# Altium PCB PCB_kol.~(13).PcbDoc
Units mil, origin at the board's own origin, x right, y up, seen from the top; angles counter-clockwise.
Board outline 2952.76 x 2952.76 mil, 4 copper layers (Top Layer, Mid 1 - POWER, Mid 2 - GND, Bottom Layer), stack 38.362 mil thick; 6 components, 21 nets, 136 pads, 182 vias.
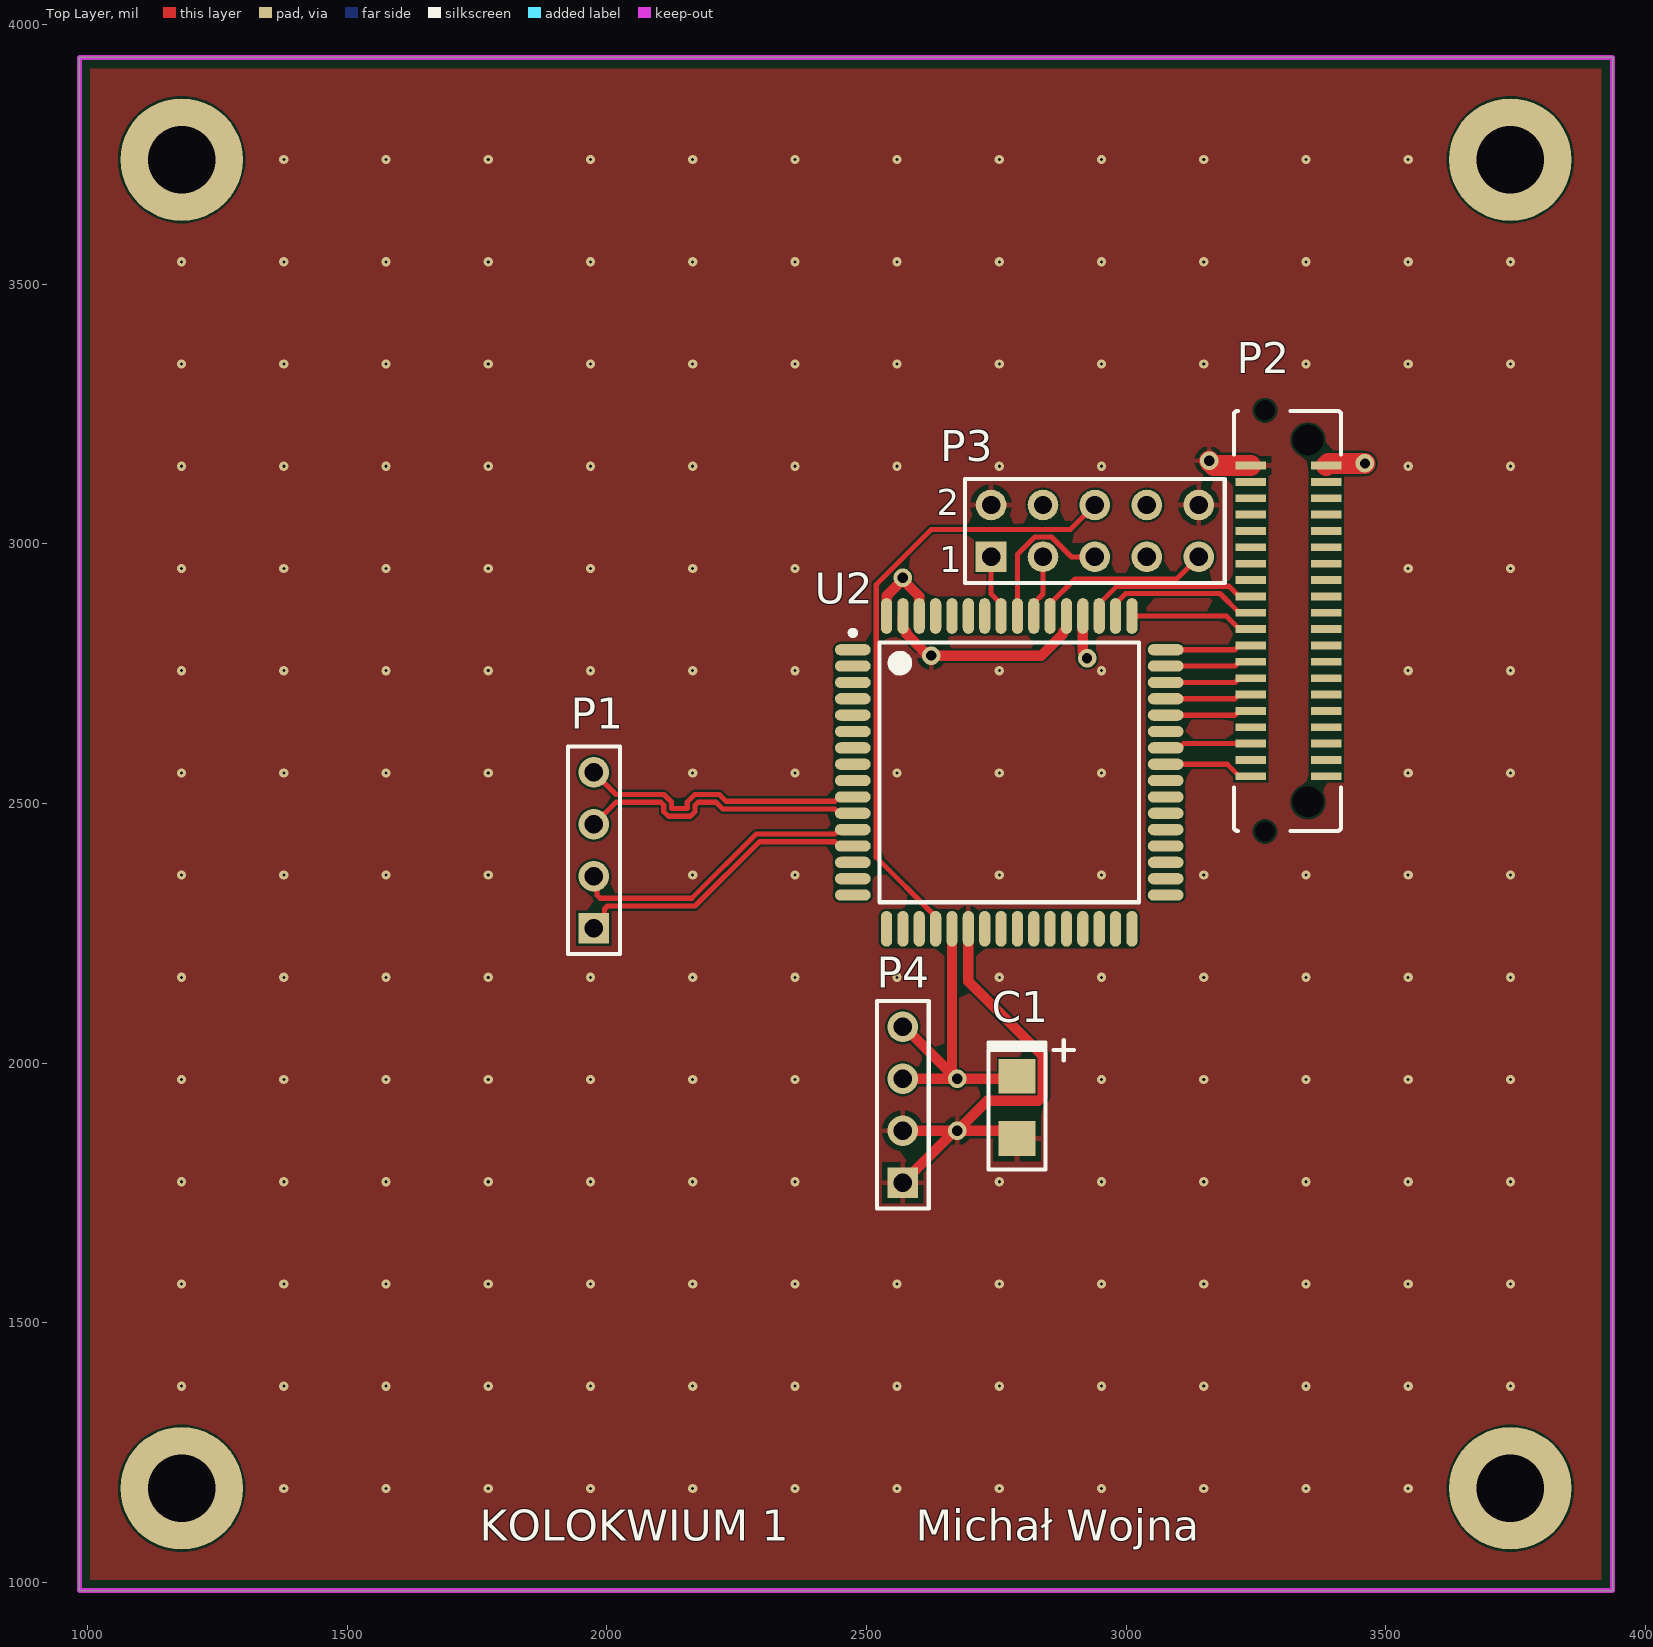
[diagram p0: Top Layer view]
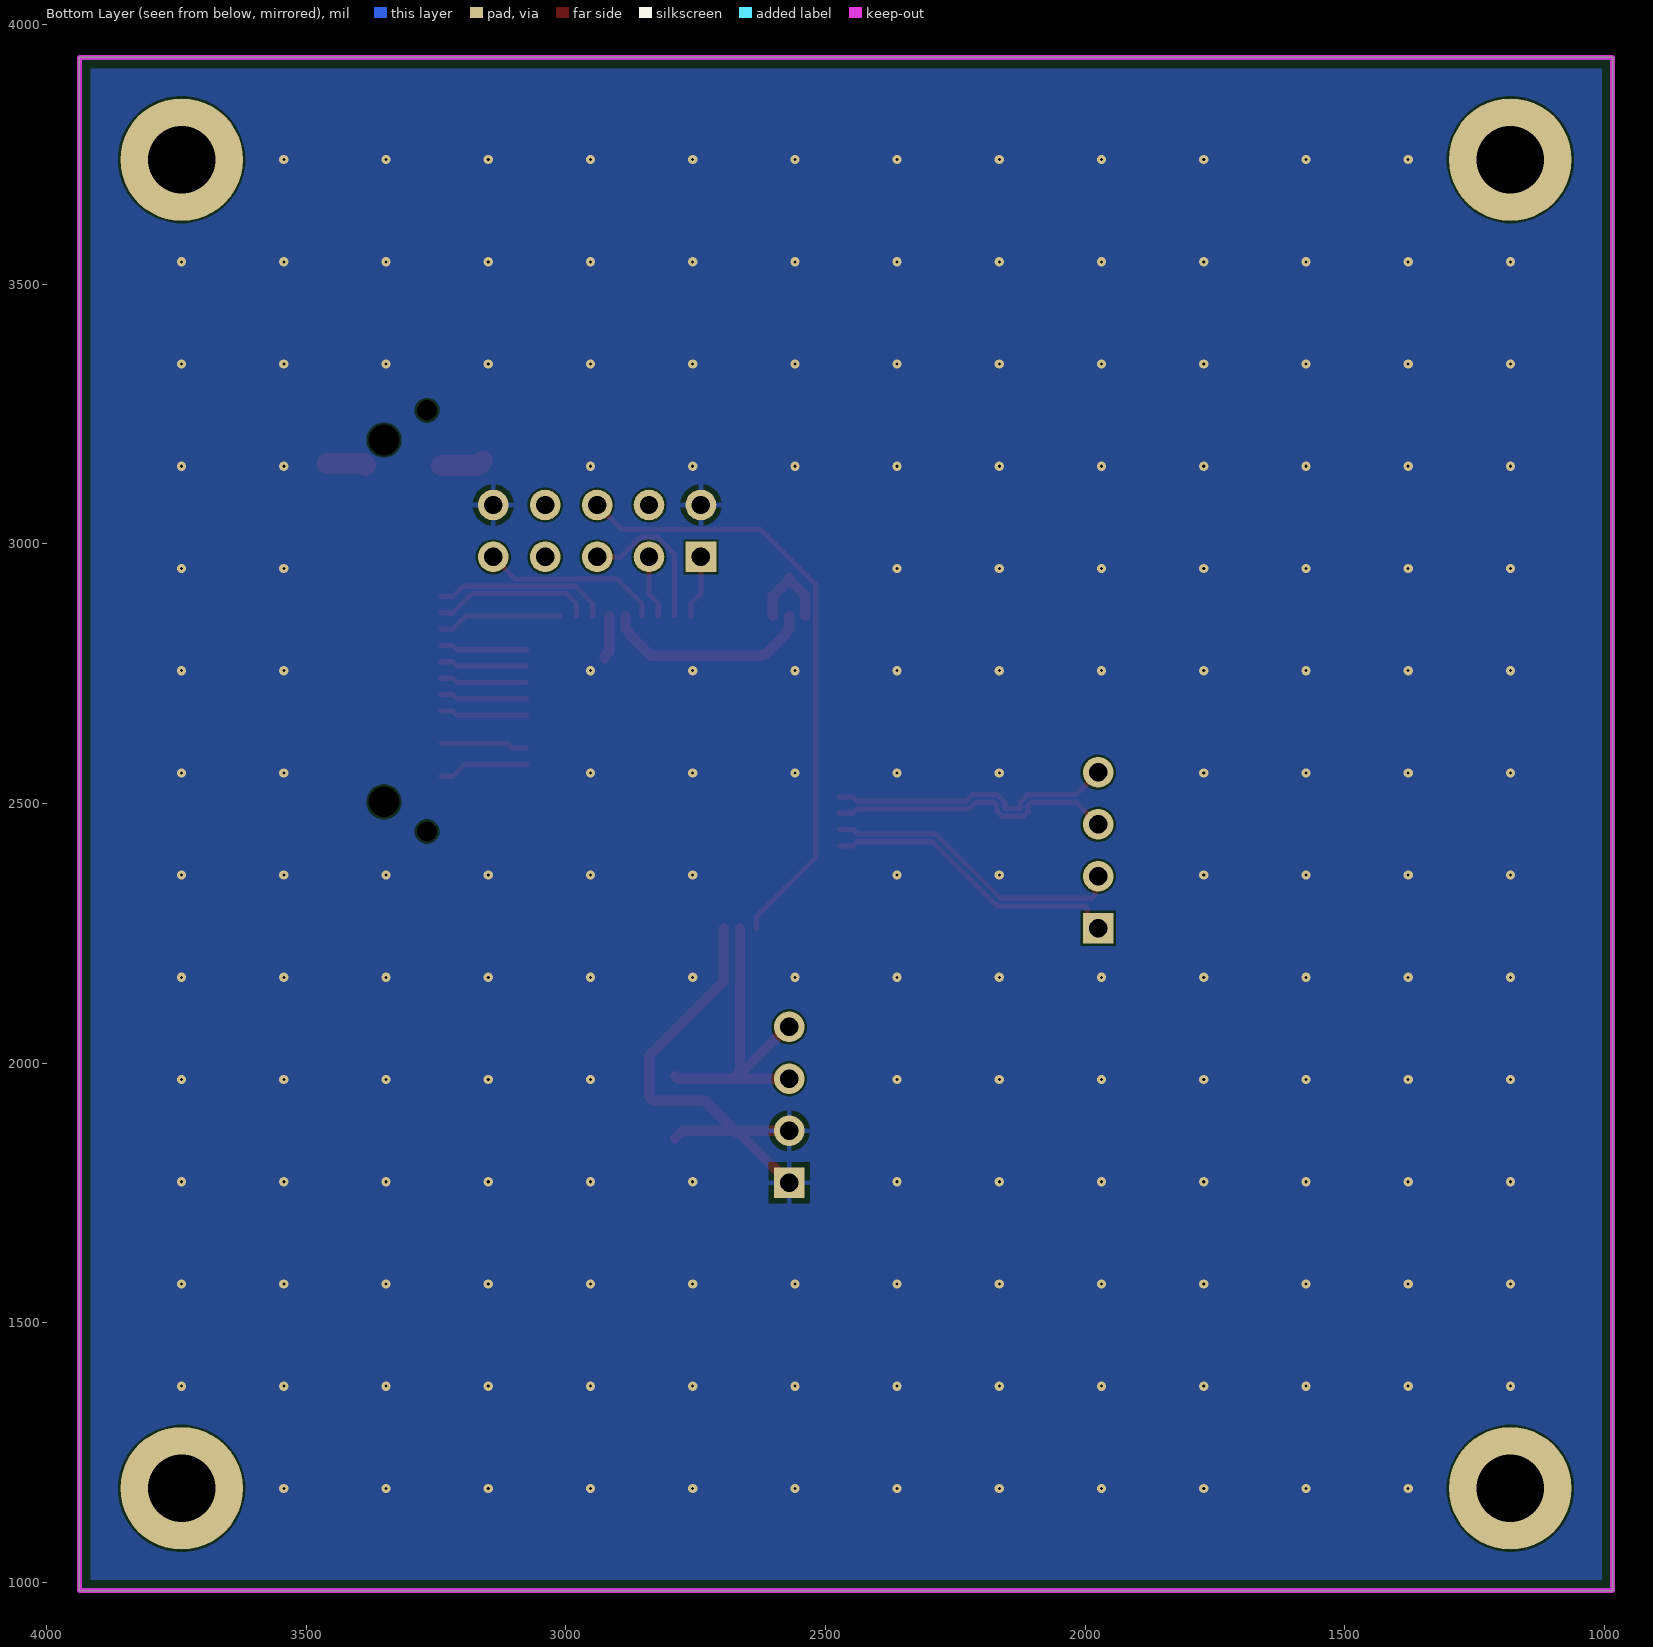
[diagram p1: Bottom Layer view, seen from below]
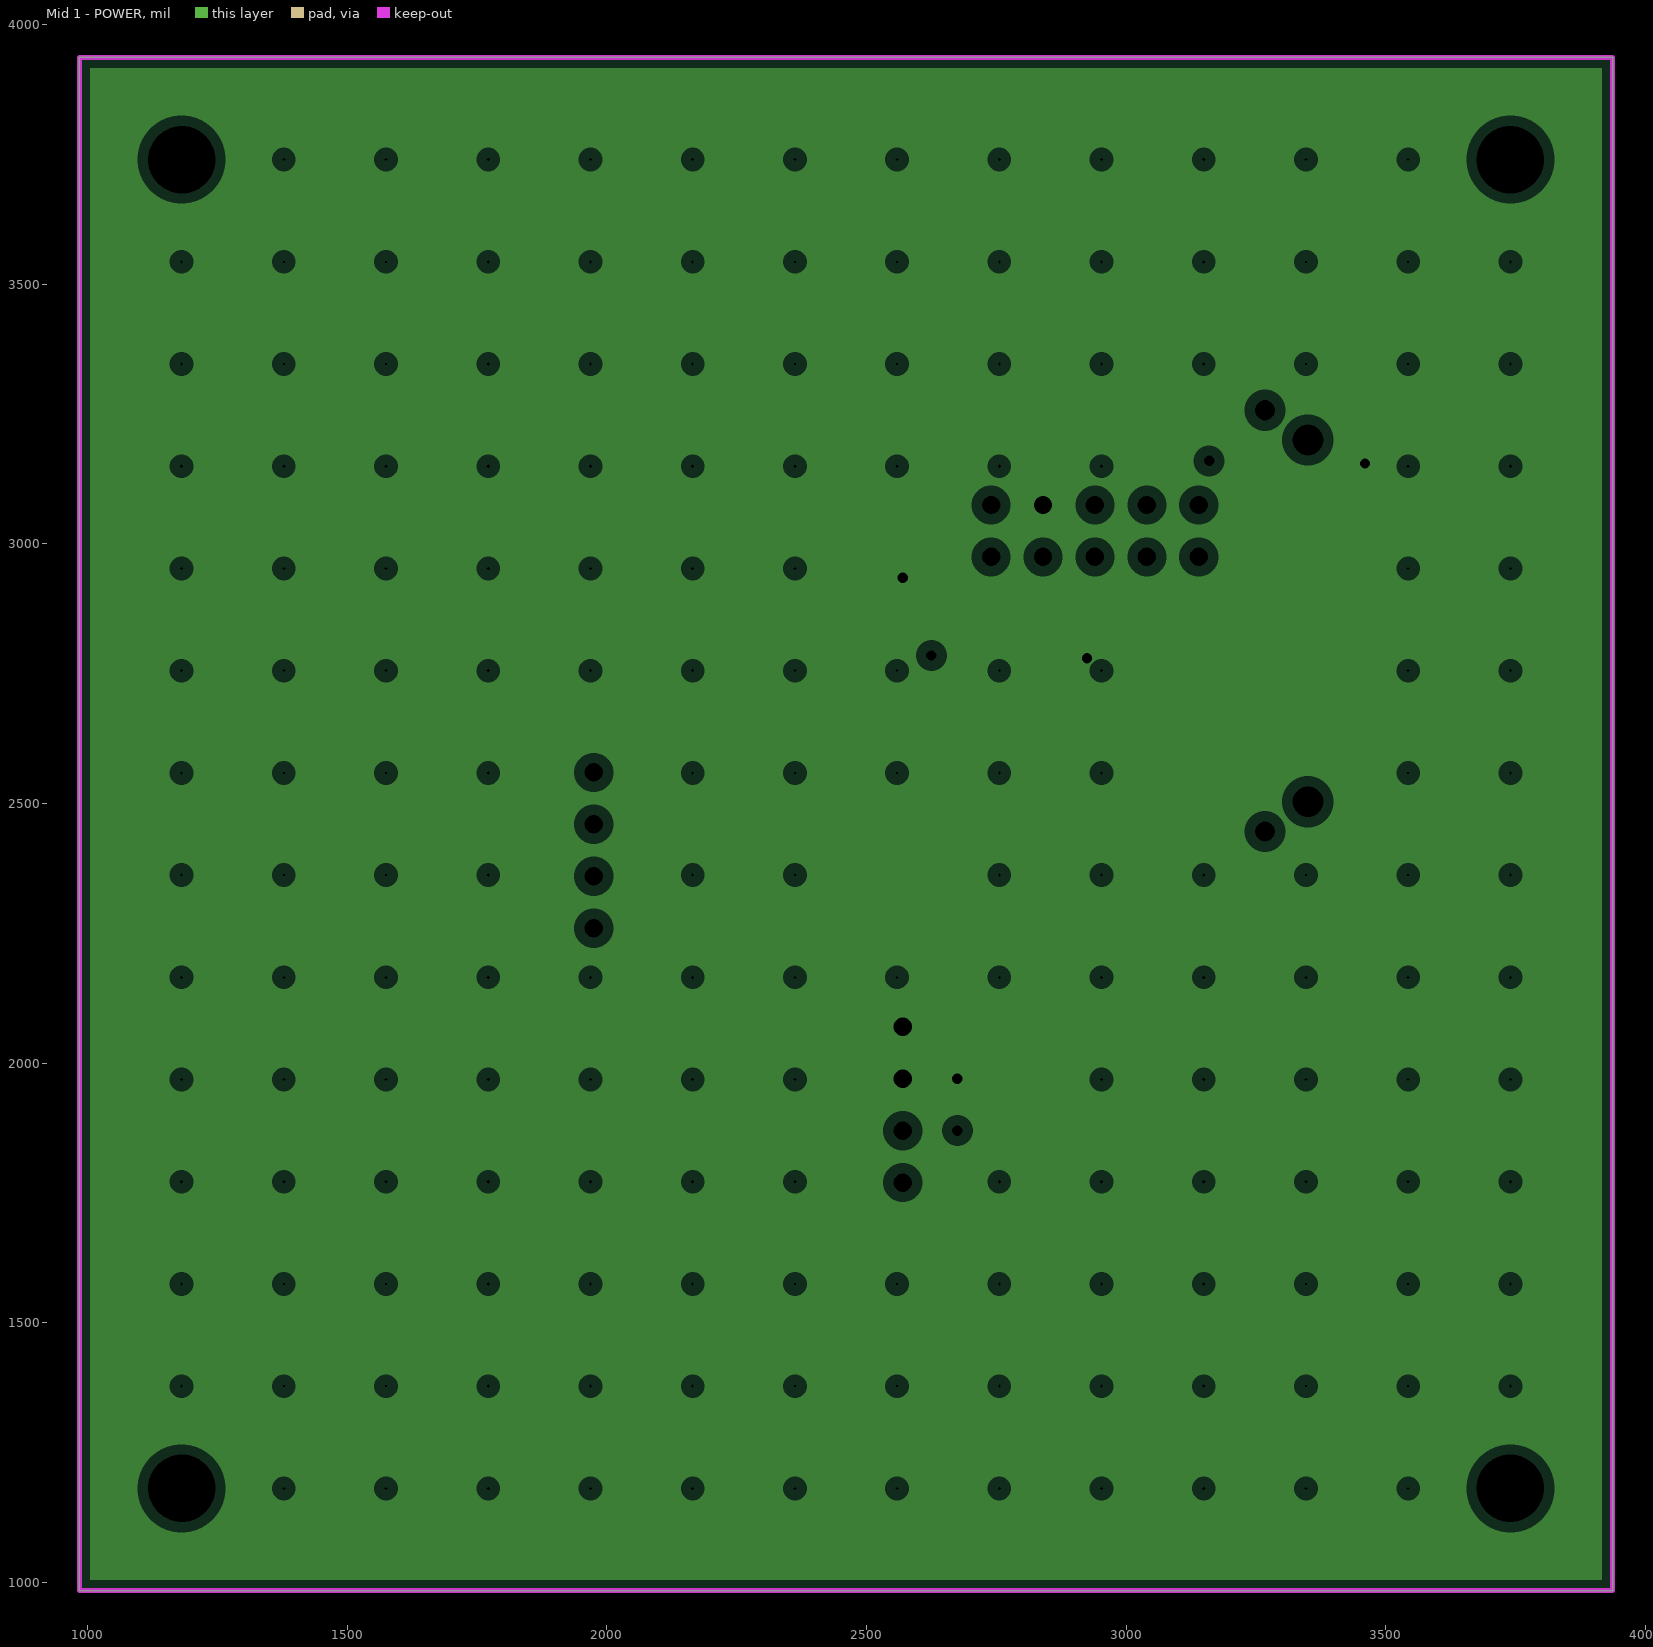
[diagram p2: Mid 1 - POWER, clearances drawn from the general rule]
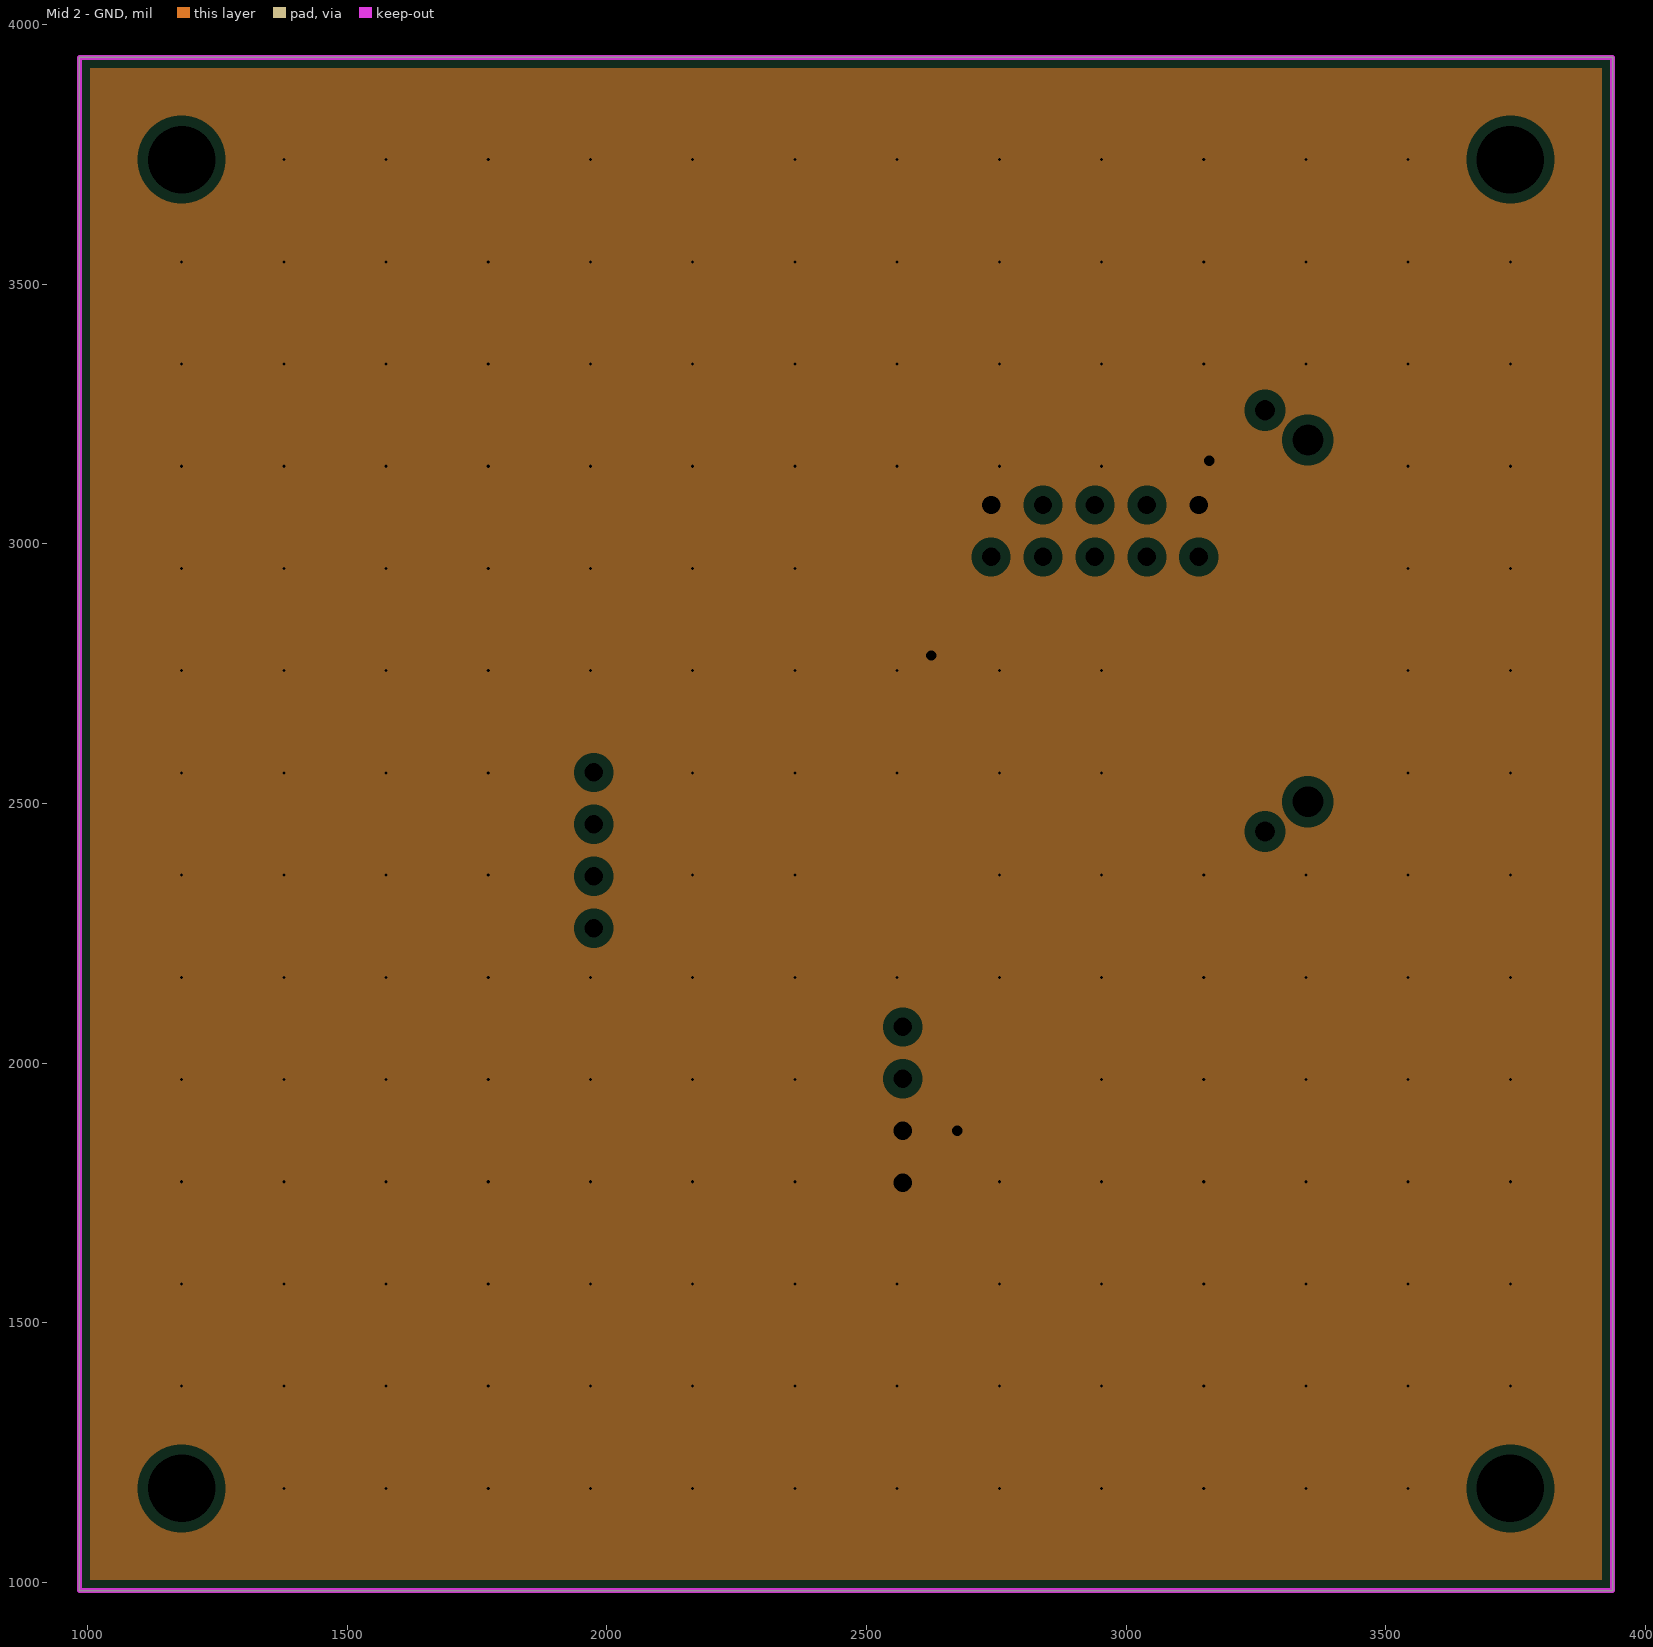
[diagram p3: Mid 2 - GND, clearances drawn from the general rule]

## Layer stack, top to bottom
Top Solder: solder mask 0.4, Solder Resist, Dk 3.5
Top Layer: signal copper 0.7087
Dielectric 1: prepreg 10.0866, Isola IS400, Dk 3.97
Mid 1 - POWER: plane copper 1.378, net 5V0
Dielectric 2: core 14.0157, Isola IS400, Dk 3.97
Mid 2 - GND: plane copper 1.378, net GND
Dielectric 3: prepreg 10.0866, Isola IS400, Dk 3.97
Bottom Layer: signal copper 0.7087
Bottom Solder: solder mask 0.4, Solder Resist, Dk 3.5

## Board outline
984.25,984.25 3937.01,984.25 3937.01,3937.01 984.25,3937.01

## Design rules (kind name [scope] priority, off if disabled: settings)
Clearance [All] p1: gap=4 ignorepadtopadclearanceinfootprint=TRUE
DiffPairsRouting [InDifferentialPairClass('All Differential Pairs')] p1: maxlimit=5 minlimit=5 mostfreqgap=5 toplayer_minwidth=10 toplayer_maxwidth=10 toplayer_prefwidth=10 bottomlayer_minwidth=10 bottomlayer_maxwidth=10 bottomlayer_prefwidth=10 impedanceprofiledriven=TRUE impedanceprofileid={655E532C-7196-4E46-AC67-4B08DF412818} impedanceprofilevalue=100.000000 maxuncoupledlength=500
HoleSize [All] p1: absolutevalues=TRUE maxlimit=130 minlimit=1 maxpercent=80.000 minpercent=20.000
MatchedLengths [InDifferentialPairClass('All Differential Pairs')] p1: tolerance=50 checknetsindiffpair=FALSE checkdiffpairvsdiffpair=TRUE checkxsignals=TRUE checkothers=TRUE
MinimumSolderMaskSliver [All] p1: minsoldermaskwidth=4
PlaneClearance [All] p1: clearance=20
PlaneConnect [(InNet('5V0') OR InNet('GND'))] p1: planeconnectstyle=Direct reliefexpansion=20 reliefentries=4 reliefconductorwidth=10 reliefairgap=10
PolygonConnect [All] p1: connectstyle=Relief reliefconductorwidth=10 reliefentries=4 polygonreliefangle="90 Angle" airgapwidth=10
RoomDefinition U_Processor [InComponentClass('U_Processor')] p1: confinementstyle=ConfineIn formatcopy=TRUE lockcomponents=FALSE outline 2419.53,2204.53 2419.53,2915.47 3130.47,2915.47 3130.47,2204.53 2913.94,1781.06 2721.06,1781.06
RoomDefinition Schemat_top [InComponentClass('Schemat_top')] p2: confinementstyle=ConfineIn formatcopy=TRUE lockcomponents=FALSE outline 1911.06,2196.06 1911.06,2623.94 2617,3138.94 3192.6,3308.58 3429.14,3308.58 3429.14,2394.88 2633.94,1706.06 2506.06,1706.06
RoutingVias [All] p1: holewidth=28 width=50 viastyle="Through Hole" minholewidth=28 minwidth=50 maxholewidth=28 maxwidth=50
SolderMaskExpansion [All] p1: expansion=2 istentingtop=FALSE
SupplyNets "Schematic Supply Nets_1" [InNet('5V0')] p1: voltage=0.000
SupplyNets "Schematic Supply Nets" [InNet('GND')] p2: voltage=0.000
Width gnd&5v0 [(InNet('5V0') OR InNet('GND'))] p1: maxlimit=100 minlimit=20 preferedwidth=40
Width Width_1 [All] p2: maxlimit=10 minlimit=10 preferedwidth=10
25 further rules are at their usual default settings.

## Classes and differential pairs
net class BUS[0..7]: BUS0 BUS1 BUS2 BUS3 BUS4 BUS5 BUS6 BUS7
component class Schemat_top: P1 P2 P3 P4
component class U_Processor: C1 C? U2
differential pair output2: +output2_P -output2_N
differential pair output1: +output1_P -output1_N

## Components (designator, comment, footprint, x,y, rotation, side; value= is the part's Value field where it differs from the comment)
C1 "22u" VJ_Tantalum_A 2790,1915 r270 top
P1 "Header 4" HDR1X4 1975,2260 r90 top
P2 "SAMTEC LSEM 40-pin" LSEM-120-03.0-L-DV-A-N-K-TR 3312.83,2851.73 r90 top
P3 "Header 5X2" HDR2X5 2740,2975 r0 top
P4 "Header 4" HDR1X4 2570,1770 r90 top
U2 "ATmega128-16AU" 64A_N 2775,2560 r0 top

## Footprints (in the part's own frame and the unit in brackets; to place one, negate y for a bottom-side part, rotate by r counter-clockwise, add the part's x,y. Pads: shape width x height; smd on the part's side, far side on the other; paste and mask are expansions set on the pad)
64A_N [mm] "Thin QFP, 64-Leads, Body 14x14mm, Pitch 0.8mm, IPC Medium Density"
  oval 1.75x0.55 smd: 1(-7.65,6) 2(-7.65,5.2) 3(-7.65,4.4) 4(-7.65,3.6) 5(-7.65,2.8) 6(-7.65,2) 7(-7.65,1.2) 8(-7.65,0.4) 9(-7.65,-0.4) 10(-7.65,-1.2) 11(-7.65,-2) 12(-7.65,-2.8) 13(-7.65,-3.6) 14(-7.65,-4.4) 15(-7.65,-5.2) 16(-7.65,-6) 33(7.65,-6) 34(7.65,-5.2) 35(7.65,-4.4) 36(7.65,-3.6) 37(7.65,-2.8) 38(7.65,-2) 39(7.65,-1.2) 40(7.65,-0.4) 41(7.65,0.4) 42(7.65,1.2) 43(7.65,2) 44(7.65,2.8) 45(7.65,3.6) 46(7.65,4.4) 47(7.65,5.2) 48(7.65,6)
  oval 0.55x1.75 smd: 17(-6,-7.65) 18(-5.2,-7.65) 19(-4.4,-7.65) 20(-3.6,-7.65) 21(-2.8,-7.65) 22(-2,-7.65) 23(-1.2,-7.65) 24(-0.4,-7.65) 25(0.4,-7.65) 26(1.2,-7.65) 27(2,-7.65) 28(2.8,-7.65) 29(3.6,-7.65) 30(4.4,-7.65) 31(5.2,-7.65) 32(6,-7.65) 49(6,7.65) 50(5.2,7.65) 51(4.4,7.65) 52(3.6,7.65) 53(2.8,7.65) 54(2,7.65) 55(1.2,7.65) 56(0.4,7.65) 57(-0.4,7.65) 58(-1.2,7.65) 59(-2,7.65) 60(-2.8,7.65) 61(-3.6,7.65) 62(-4.4,7.65) 63(-5.2,7.65) 64(-6,7.65)
  silkscreen extent -7.77,-6.35 6.35,6.95, body extent -7,-7 7,7, height 1.2
HDR1X4 [mm] "Connector; Header; 4 Position"
  rect 1.5x1.5 hole 0.9: 1(0,0)
  round 1.5 hole 0.9: 2(2.54,0) 3(5.08,0) 4(7.62,0)
  silkscreen extent -1.27,-1.27 8.89,1.27
HDR2X5 [mm] "Connector; Header; 5x2 Position"
  rect 1.5x1.5 hole 0.9: 1(0,0)
  round 1.5 hole 0.9: 2(0,2.54) 3(2.54,0) 4(2.54,2.54) 5(5.08,0) 6(5.08,2.54) 7(7.62,0) 8(7.62,2.54) 9(10.16,0) 10(10.16,2.54)
  silkscreen extent -1.27,-1.27 11.43,3.81
LSEM-120-03.0-L-DV-A-N-K-TR [mm] "LSEM 0.8mm Razor Beam Hermaphroditic Connector 40-pin"
  round 0 hole 1 unplated: 0(-10.3,1.15) 0(10.3,1.15)
  round 2 on Top Paste paste+2: 0(-10.3,1.15) 0(10.3,1.15)
  round 2.1 on Top Solder paste+2: 0(-10.3,1.15) 0(10.3,1.15)
  round 0 hole 1.5 unplated: 0(-8.85,-0.95) 0(8.85,-0.95)
  rect 0.38x1.5 smd: 1(7.6,-1.85) 2(7.6,1.85) 3(6.8,-1.85) 4(6.8,1.85) 5(6,-1.85) 6(6,1.85) 7(5.2,-1.85) 8(5.2,1.85) 9(4.4,-1.85) 10(4.4,1.85) 11(3.6,-1.85) 12(3.6,1.85) 13(2.8,-1.85) 14(2.8,1.85) 15(2,-1.85) 16(2,1.85) 17(1.2,-1.85) 18(1.2,1.85) 19(0.4,-1.85) 20(0.4,1.85) 21(-0.4,-1.85) 22(-0.4,1.85) 23(-1.2,-1.85) 24(-1.2,1.85) 25(-2,-1.85) 26(-2,1.85) 27(-2.8,-1.85) 28(-2.8,1.85) 29(-3.6,-1.85) 30(-3.6,1.85) 31(-4.4,-1.85) 32(-4.4,1.85) 33(-5.2,-1.85) 34(-5.2,1.85) 35(-6,-1.85) 36(-6,1.85) 37(-6.8,-1.85) 38(-6.8,1.85) 39(-7.6,-1.85) 40(-7.6,1.85)
  silkscreen extent -10.28,-2.57 10.28,2.68, body extent -10.2,-2.7 10.2,2.8, height 4.58
VJ_Tantalum_A [mm]
  rect 1.7x1.8 smd: 1(-1.525,0) 2(1.525,0)
  silkscreen extent -3.3,-1.4 3.05,2.79, body extent -1.85,-0.89 1.85,0.89, height 1.6

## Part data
C1: library part Capacitor_polarized, Manufacturer=VJ, Part Number=293D223X9016D2TE3, Rated Voltage=16V, Tolerance=10%
P1 P4: "Header, 4-Pin"
P2: "Component desciption", Manufacture=SAMTEC, Part Number=LSEM-120-03.0-L-DV-A-N-K-TR, Supplier Part Number 1=2433813
P3: "Header, 5-Pin, Dual row"
U2: "8-bit AVR Microcontroller, 4.5-5.5V, 128KB Flash, 4KB EEPROM, 4KB SRAM, 64-pin TQFP, Industrial Grade (-40°C to 85°C)"

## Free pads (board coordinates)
  round 236.22 hole 129.92: 0(1181.1,1181.1) 0(1181.1,3740.16) 0(3740.16,1181.1) 0(3740.16,3740.16)

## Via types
v1: diameter 17.72/17.72 (per signal layer), hole 5.91, Top Layer to Bottom Layer, 175 vias
v2: diameter 35.43, hole 19.68, Top Layer to Mid 1 - POWER, tented both sides, 4 vias
v3: diameter 35.43, hole 19.68, Top Layer to Mid 2 - GND, tented both sides, 3 vias

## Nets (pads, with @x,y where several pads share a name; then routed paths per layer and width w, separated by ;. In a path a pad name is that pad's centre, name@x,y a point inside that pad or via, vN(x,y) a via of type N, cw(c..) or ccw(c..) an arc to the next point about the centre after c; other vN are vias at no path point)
5V0: C1.1 P2.1 P3.4 P4.3 P4.4 U2.21 U2.52 U2.62 U2.64 | length 989.2
  Top Layer w20: U2.64 2539.1,2861.5 2539.1,2899.92 v2@2570,2930.82 ; P4.3 v2@2672.5,1970 ; P4.4 2572.5,2070 v2@2672.5,1970 ; v2(2570,2935) v2@2570,2930.82 ; U2.62 2601.46,2861.5 2601.46,2899.37 v2@2570,2930.82 ; U2.21 2664.76,1984.41 2675,1974.18 v2(2675,1970) ; C1.1 2784.96,1970 v2(2675,1970) ; U2.52 2916.73,2792.44 2925,2784.18 v2(2925,2780) ; v2@2672.5,1970 v2(2675,1970)
  Top Layer w40: P2.1 3389.72,3155 v2(3460,3155)
BUS0: P2.18 U2.51 | length 337.5
  Top Layer w10: U2.51 2948.23,2884.8 2982.05,2918.63 3198.3,2918.63 3217.95,2898.98 P2.18
BUS1: P2.20 U2.50 | length 307.5
  Top Layer w10: U2.50 2979.72,2884.8 2999.55,2904.63 3180.8,2904.63 3217.95,2867.48 P2.20
BUS2: P2.22 U2.49 | length 239.2
  Top Layer w10: U2.49 3192.76,2861.18 3217.95,2835.98 P2.22
BUS3: P2.24 U2.48 | length 167.2
  Top Layer w10: U2.48 3209.69,2796.22 3217.95,2804.49 P2.24
BUS4: P2.26 U2.47 | length 167.2
  Top Layer w10: U2.47 3209.69,2764.72 3217.95,2772.99 P2.26
BUS5: P2.28 U2.46 | length 167.2
  Top Layer w10: U2.46 3209.68,2733.23 3217.95,2741.5 P2.28
BUS6: P2.30 U2.45 | length 167.2
  Top Layer w10: U2.45 3209.69,2701.73 3217.95,2710 P2.30
BUS7: P2.32 U2.44 | length 167.2
  Top Layer w10: U2.44 3209.69,2670.24 3217.95,2678.5 P2.32
GND: C1.2 P2.2 P3.2 P3.10 P4.1 P4.2 U2.22 U2.53 U2.63 | length 1440.4
  Top Layer w20: P4.1 2667.05,1867.05 2672.05,1867.05 v3(2675,1870) ; P4.2 v3(2675,1870) ; U2.63 2570.28,2837.11 2576.95,2830.44 2576.95,2827.28 2616.27,2787.95 2622.05,2787.95 v3(2625,2785) 2836.29,2785 2878.57,2827.28 2878.57,2830.44 2885.24,2837.11 U2.53 ; U2.22 2696.26,2157.48 2839.43,2014.3 2839.43,1935.78 2831.23,1927.57 2732.57,1927.57 v3(2675,1870) ; C1.2 2774.96,1870 v3(2675,1870)
  Top Layer w40: v3(3160,3160) 3169.06,3150.94 P2.2
  other v1: 1377.95,1181.1 1574.8,1181.1 1771.65,1181.1 1968.5,1181.1 2165.35,1181.1 2362.2,1181.1 2559.05,1181.1 2755.9,1181.1 2952.75,1181.1 3149.6,1181.1 3346.45,1181.1 3543.3,1181.1 1181.1,1377.95 1377.95,1377.95 1574.8,1377.95 1771.65,1377.95 1968.5,1377.95 2165.35,1377.95 2362.2,1377.95 2559.05,1377.95 2755.9,1377.95 2952.75,1377.95 3149.6,1377.95 3346.45,1377.95 3543.3,1377.95 3740.15,1377.95 1181.1,1574.8 1377.95,1574.8 1574.8,1574.8 1771.65,1574.8 1968.5,1574.8 2165.35,1574.8 2362.2,1574.8 2559.05,1574.8 2755.9,1574.8 2952.75,1574.8 3149.6,1574.8 3346.45,1574.8 3543.3,1574.8 3740.15,1574.8 1181.1,1771.65 1377.95,1771.65 1574.8,1771.65 1771.65,1771.65 1968.5,1771.65 2165.35,1771.65 2362.2,1771.65 2755.9,1771.65 2952.75,1771.65 3149.6,1771.65 3346.45,1771.65 3543.3,1771.65 3740.15,1771.65 1181.1,1968.5 1377.95,1968.5 1574.8,1968.5 1771.65,1968.5 1968.5,1968.5 2165.35,1968.5 2362.2,1968.5 2952.75,1968.5 3149.6,1968.5 3346.45,1968.5 3543.3,1968.5 3740.15,1968.5 1181.1,2165.35 1377.95,2165.35 1574.8,2165.35 1771.65,2165.35 1968.5,2165.35 2165.35,2165.35 2362.2,2165.35 2559.05,2165.35 2755.9,2165.35 2952.75,2165.35 3149.6,2165.35 3346.45,2165.35 3543.3,2165.35 3740.15,2165.35 1181.1,2362.2 1377.95,2362.2 1574.8,2362.2 1771.65,2362.2 2165.35,2362.2 2362.2,2362.2 2755.9,2362.2 2952.75,2362.2 3149.6,2362.2 3346.45,2362.2 3543.3,2362.2 3740.15,2362.2 1181.1,2559.05 1377.95,2559.05 1574.8,2559.05 1771.65,2559.05 2165.35,2559.05 2362.2,2559.05 2559.05,2559.05 2755.9,2559.05 2952.75,2559.05 3543.3,2559.05 3740.15,2559.05 1181.1,2755.9 1377.95,2755.9 1574.8,2755.9 1771.65,2755.9 1968.5,2755.9 2165.35,2755.9 2362.2,2755.9 2559.05,2755.9 2755.9,2755.9 2952.75,2755.9 3543.3,2755.9 3740.15,2755.9 1181.1,2952.75 1377.95,2952.75 1574.8,2952.75 1771.65,2952.75 1968.5,2952.75 2165.35,2952.75 2362.2,2952.75 3543.3,2952.75 3740.15,2952.75 1181.1,3149.6 1377.95,3149.6 1574.8,3149.6 1771.65,3149.6 1968.5,3149.6 2165.35,3149.6 2362.2,3149.6 2559.05,3149.6 2755.9,3149.6 2952.75,3149.6 3543.3,3149.6 3740.15,3149.6 1181.1,3346.45 1377.95,3346.45 1574.8,3346.45 1771.65,3346.45 1968.5,3346.45 2165.35,3346.45 2362.2,3346.45 2559.05,3346.45 2755.9,3346.45 2952.75,3346.45 3149.6,3346.45 3346.45,3346.45 3543.3,3346.45 3740.15,3346.45 1181.1,3543.3 1377.95,3543.3 1574.8,3543.3 1771.65,3543.3 1968.5,3543.3 2165.35,3543.3 2362.2,3543.3 2559.05,3543.3 2755.9,3543.3 2952.75,3543.3 3149.6,3543.3 3346.45,3543.3 3543.3,3543.3 3740.15,3543.3 1377.95,3740.15 1574.8,3740.15 1771.65,3740.15 1968.5,3740.15 2165.35,3740.15 2362.2,3740.15 2559.05,3740.15 2755.9,3740.15 2952.75,3740.15 3149.6,3740.15 3346.45,3740.15 3543.3,3740.15
out1: P2.40 U2.41 | length 173.4
  Top Layer w10: U2.41 3194.72,2575.75 3217.95,2552.52 P2.40
out2: P2.36 U2.42 | length 167.2
  Top Layer w10: U2.42 3102.96,2607.24 3111.22,2615.51 P2.36
output1_N: P1.4 U2.10 | length 562
  Top Layer w10: P1.4 2017.5,2517.5 2060,2517.5 2110.1,2517.5 2124.75,2502.86 2124.75,2490.52 2154.75,2490.52 2154.75,2502.86 2169.39,2517.5 2185,2517.5 2216.63,2517.5 2229.62,2504.51 2438.8,2504.51 2447.04,2512.76 U2.10
output1_P: P1.3 U2.11 | length 562
  Top Layer w10: P1.3 2017.5,2502.5 2060,2502.5 2103.89,2502.5 2109.75,2496.64 2109.75,2484.3 2118.53,2475.52 2160.96,2475.52 2169.75,2484.3 2169.75,2496.64 2175.61,2502.5 2185,2502.5 2210.41,2502.5 2223.41,2489.51 2438.8,2489.51 2447.04,2481.26 U2.11
output2_N: P1.2 U2.12 | length 589
  Top Layer w10: P1.2 1981.33,2353.67 1981.33,2323.36 1987.19,2317.5 2163.69,2317.5 2287.7,2441.52 2438.8,2441.52 2447.04,2449.76 U2.12
output2_P: P1.1 U2.13 | length 580.5
  Top Layer w10: P1.1 1995.7,2280.7 1995.7,2296.64 2001.56,2302.5 2169.9,2302.5 2293.92,2426.52 2438.8,2426.52 2447.04,2418.27 U2.13
R\E\S\E\T\: P3.6 U2.20 | length 1194.8
  Top Layer w10: U2.20 2633.27,2282.44 2518.95,2396.76 2518.95,2921.74 2624.75,3027.53 2892.53,3027.53 P3.6
TCK: P3.1 U2.57 | length 121.8
  Top Layer w10: P3.1 2740,2904.06 2759.25,2884.8 U2.57
TDI: P3.9 U2.54 | length 347.2
  Top Layer w10: U2.54 2853.74,2884.8 2901.57,2932.63 3097.63,2932.63 P3.9
TDO: P3.3 U2.55 | length 121.2
  Top Layer w10: U2.55 2822.24,2885.82 2840,2903.57 P3.3
TMS: P3.5 U2.56 | length 298.1
  Top Layer w10: U2.56 2790.75,2980.23 2824.04,3013.53 2856.12,3013.53 2894.65,2975 P3.5
pads on no net: P2.0 P2.3 P2.4 P2.5 P2.6 P2.7 P2.8 P2.9 P2.10 P2.11 P2.12 P2.13 P2.14 P2.15 P2.16 P2.17 P2.19 P2.21 P2.23 P2.25 P2.27 P2.29 P2.31 P2.33 P2.34 P2.35 P2.37 P2.38 P2.39 P3.7 P3.8 U2.1 U2.2 U2.3 U2.4 U2.5 U2.6 U2.7 U2.8 U2.9 U2.14 U2.15 U2.16 U2.17 U2.18 U2.19 U2.23 U2.24 U2.25 U2.26 U2.27 U2.28 U2.29 U2.30 U2.31 U2.32 U2.33 U2.34 U2.35 U2.36 U2.37 U2.38 U2.39 U2.40 U2.43 U2.58 U2.59 U2.60 U2.61

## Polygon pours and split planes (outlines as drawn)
GND on Bottom Layer "GND_L04_P001" (solid, pour order 1): 1005,3915 3915,3915 3915,1005 1005,1005
GND on Top Layer "GND_L01_P000" (solid, pour order 0): 1005,3915 3915,3915 3915,1005 1005,1005
5V0 on Mid 1 - POWER (split plane): 3916.91,1004.35 1004.35,1004.35 1004.35,3916.91 3916.91,3916.91
GND on Mid 2 - GND (split plane): 3916.91,1004.35 1004.35,1004.35 1004.35,3916.91 3916.91,3916.91

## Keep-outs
Keep-Out Layer:
  the board outline again, w10

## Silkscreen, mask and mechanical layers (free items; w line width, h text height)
Top Overlay:
  text "KOLOKWIUM 1" at 1755,1080 h60
  text "Michał Wojna" at 2595,1080 h60

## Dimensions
1181.1,3740.16 to 3740.16,3740.16 on M5 Dimensions
3937.01,984.25 to 3937.01,3937.01 on M5 Dimensions
984.25,984.25 to 3937.01,984.25 on M5 Dimensions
